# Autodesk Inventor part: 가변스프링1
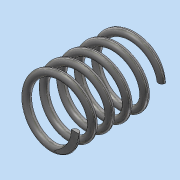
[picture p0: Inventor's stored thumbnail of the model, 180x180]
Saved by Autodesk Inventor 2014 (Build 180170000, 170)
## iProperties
Created: 2018-10
Part Number: 가변스프링1
Material: 스테인레스 스틸
Document SubType Name: Modeling
Designer: kb542
Density: 8.08 g/cm^3
Appearance: 반연마
Mass: 6.26769 g
Surface Area: 15.7757 cm^2
Volume: 0.775705 cm^3
Author: kb542
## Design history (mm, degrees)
sketch "스케치1"
  geometry: L1 (0, 0)-(8, 0); L2 (8, 0)-(8, 24.528); L3 (8, 24.528)-(0, 24.528); L4 (0, 24.528)-(0, 0); C1 r 1 at (8, 0)
  constraints: 8 end point, 2 parallel, 1 centre point, 1 coincident, 1 horizontal, 1 perpendicular
  dimensions: "d0" = 24.52794 distance between parallel lines of L1 L3 (derived); "d1" = 2 diameter of C1; "d2" = 16 diameter of L2 L4
feature "코일1" sketch "스케치1" pitch "d3" = 10; turns "d5" = 5; dims "d4" = 24.52794 (= d0), "d6" = 0, angle "d7" = 90 deg, angle "d8" = 90 deg, "d9" = 0, "d10" = 0
sketch "스케치2"
  geometry: L1 (-9, 0)-(-7, 0) reference; 1 further point
  constraints: 1 horizontal alignment
extrude "돌출1" cut sketch "스케치2" distance "d11" = 10; taper "d12" = 0 deg
node "작업 평면1"
sketch "스케치3"
  geometry: L1 (-7, 0)-(-9, 0) reference; 1 further point
  constraints: 1 horizontal alignment
extrude "돌출2" cut sketch "스케치3" distance "d13" = 10; taper "d14" = 0 deg
node "솔리드1"
node "절단 모서리 투영1"
node "절단 모서리 투영2"
